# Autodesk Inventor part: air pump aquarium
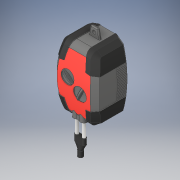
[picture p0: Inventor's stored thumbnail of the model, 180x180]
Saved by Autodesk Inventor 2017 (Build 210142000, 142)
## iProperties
Created: 2020-03
Part Number: air pump aquarium
Material: Generic
Description: STEP AP214
Document SubType Name: Modeling
Designer: user
Density: 1 g/cm^3
Appearance: Default
Title: air pump aquarium.STEP
Revision Number: ANY
Sending System: SolidWorks 2018
Preprocessor: SwSTEP 2.0
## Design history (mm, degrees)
loft "NONE"
loft "Loft1"
loft "Yükseklik-Ekstrüzyon9"
body "Solid1"
body "Solid2"
body "Solid3"
